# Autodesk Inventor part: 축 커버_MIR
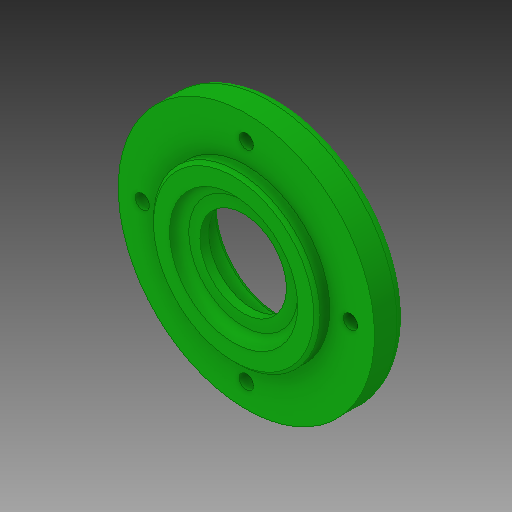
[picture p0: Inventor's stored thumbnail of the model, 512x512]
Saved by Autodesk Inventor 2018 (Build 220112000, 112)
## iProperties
Created: 2015-10
Part Number: 축 커버_MIR
Material: 일반
Document SubType Name: Modeling
Designer: expoc
Density: 1 g/cm^3
Appearance: 기본값
Author: mdu
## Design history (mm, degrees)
derived "축 커버.ipt"
  sketch "스케치1"
    geometry: C1 r 40 at (0, 0) reference; C2 r 26 at (0, 0) reference; 1 further point
    dimensions: "d0" = 10 dimension on point (0, 0) C1.centre C1 C2.centre C2
  sketch "스케치2"
    geometry: C1 r 20 at (0, 0) reference; 1 further point
    dimensions: "d0" = 10 dimension on point (0, 0) C1.centre C1
  sketch "스케치3"
    geometry: C1 r 1.621 at (0, 32.5) reference; 1 further point
    dimensions: "d0" = 10 dimension on point (0, 0) C1.centre C1
feature "솔리드1::축 커버.ipt"
tag "피쳐 태그1"
node "솔리드1"
